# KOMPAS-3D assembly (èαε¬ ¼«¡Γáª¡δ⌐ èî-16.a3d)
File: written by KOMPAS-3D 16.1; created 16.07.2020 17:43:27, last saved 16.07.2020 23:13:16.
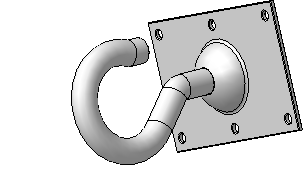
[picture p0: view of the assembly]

Referenced files in D:\Новая папка\работа\Чертежи\Крюк\: Основание.m3d, Крюк.m3d
Referenced files: GRAPHIC.TDP
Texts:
  Body Specification ( left align )
  Body Specificaton ( centered )
  (ф) 002 Крюк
